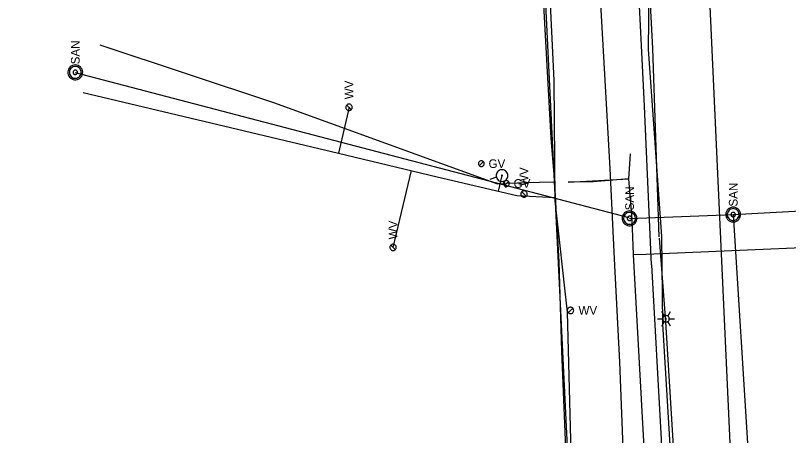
# Model space of a CAD drawing. Extents: x 596028 to 606371, y 330010 to 403088.
# Drawn here: x 604597.6 to 604941.1, y 334107.4 to 334294 of the extents above; entities that cross this region are included whole.
import ezdxf

# ---------------------------------------------------------------- set-up
doc = ezdxf.new("R2010")
doc.units = 0
for name, color, linetype in [('E_FTMS_Conduit', 7, 'Continuous'), ('E_LTG', 7, 'Continuous'), ('E_LTG_CID', 7, 'Continuous'), ('E_UTL_E_UG', 7, 'Continuous'), ('E_UTL_FO_UG_QWEST', 7, 'Continuous'), ('E_UTL_G', 7, 'Continuous'), ('E_UTL_G_UG', 7, 'Continuous'), ('E_UTL_SAN_MH', 7, 'Continuous'), ('E_UTL_SAN_UG', 7, 'Continuous'), ('E_UTL_SAN_UG_MMSD', 7, 'Continuous'), ('E_UTL_T_UG', 7, 'Continuous'), ('E_UTL_W', 7, 'Continuous'), ('E_UTL_W_UG', 7, 'Continuous'), ('E_UTL_WHydrant', 7, 'Continuous')]:
    doc.layers.add(name, color=color, linetype=linetype)

msp = doc.modelspace()

# ---------------------------------------------------------------- linework, layer by layer
at = {"layer": 'E_FTMS_Conduit'}
for points in [[(604884.79, 334195.8), (604878.86, 334279.06), (604879.25, 334317.86), (604874.33, 334402.45), (604871.01, 334441.38), (604869.22, 334499.65), (604867.19, 334547.69), (604865.66, 334623.82), (604860.3, 334662.92), (604859.68, 334742.73)], [(604896.64, 333466.11), (604897.17, 333555.99), (604901.76, 333584.15), (604905.09, 333639.3), (604905.9, 333684.1), (604904.77, 333712.67), (604904.93, 333775.72), (604905.22, 333800.4), (604903.67, 333828.24), (604898.91, 333896.44), (604894.79, 333935.39), (604893.25, 333968.09), (604888.86, 334043.3), (604889.85, 334080.96), (604885.17, 334157.03), (604884.79, 334195.8)]]:
    msp.add_lwpolyline(points, dxfattribs=at)
at = {"layer": 'E_LTG'}
for points in [[(604885.95, 334160.45), (604884.75, 334162.51)], [(604887.37, 334160.45), (604888.57, 334162.51)], [(604882.85, 334159.21), (604885.23, 334159.21)], [(604888.09, 334159.21), (604888.06, 334159.48), (604887.99, 334159.74), (604887.86, 334159.98), (604887.69, 334160.2), (604887.49, 334160.38), (604887.25, 334160.51), (604887, 334160.6), (604886.73, 334160.64), (604886.46, 334160.63), (604886.19, 334160.56), (604885.95, 334160.45), (604885.72, 334160.29), (604885.54, 334160.1), (604885.39, 334159.87), (604885.29, 334159.61), (604885.24, 334159.35), (604885.24, 334159.08), (604885.29, 334158.81), (604885.39, 334158.56), (604885.54, 334158.33), (604885.72, 334158.13), (604885.95, 334157.97), (604886.19, 334157.86), (604886.46, 334157.8), (604886.73, 334157.78), (604887, 334157.82), (604887.25, 334157.91), (604887.49, 334158.05), (604887.69, 334158.23), (604887.86, 334158.44), (604887.99, 334158.68), (604888.06, 334158.94), (604888.09, 334159.21)], [(604888.09, 334159.21), (604888.06, 334159.48), (604887.99, 334159.74), (604887.86, 334159.98), (604887.69, 334160.2), (604887.49, 334160.38), (604887.25, 334160.51), (604887, 334160.6), (604886.73, 334160.64), (604886.46, 334160.63), (604886.19, 334160.56), (604885.95, 334160.45), (604885.72, 334160.29), (604885.54, 334160.1), (604885.39, 334159.87), (604885.29, 334159.61), (604885.24, 334159.35), (604885.24, 334159.08), (604885.29, 334158.81), (604885.39, 334158.56), (604885.54, 334158.33), (604885.72, 334158.13), (604885.95, 334157.97), (604886.19, 334157.86), (604886.46, 334157.8), (604886.73, 334157.78), (604887, 334157.82), (604887.25, 334157.91), (604887.49, 334158.05), (604887.69, 334158.23), (604887.86, 334158.44), (604887.99, 334158.68), (604888.06, 334158.94), (604888.09, 334159.21)], [(604888.09, 334159.21), (604888.06, 334159.48), (604887.99, 334159.74), (604887.86, 334159.98), (604887.69, 334160.2), (604887.49, 334160.38), (604887.25, 334160.51), (604887, 334160.6), (604886.73, 334160.64), (604886.46, 334160.63), (604886.19, 334160.56), (604885.95, 334160.45), (604885.72, 334160.29), (604885.54, 334160.1), (604885.39, 334159.87), (604885.29, 334159.61), (604885.24, 334159.35), (604885.24, 334159.08), (604885.29, 334158.81), (604885.39, 334158.56), (604885.54, 334158.33), (604885.72, 334158.13), (604885.95, 334157.97), (604886.19, 334157.86), (604886.46, 334157.8), (604886.73, 334157.78), (604887, 334157.82), (604887.25, 334157.91), (604887.49, 334158.05), (604887.69, 334158.23), (604887.86, 334158.44), (604887.99, 334158.68), (604888.06, 334158.94), (604888.09, 334159.21)], [(604886.78, 334159.21), (604886.78, 334159.23), (604886.77, 334159.26), (604886.76, 334159.28), (604886.75, 334159.29), (604886.73, 334159.31), (604886.71, 334159.32), (604886.69, 334159.33), (604886.67, 334159.33), (604886.64, 334159.33), (604886.62, 334159.32), (604886.6, 334159.31), (604886.58, 334159.3), (604886.57, 334159.29), (604886.55, 334159.27), (604886.55, 334159.25), (604886.54, 334159.22), (604886.54, 334159.2), (604886.55, 334159.18), (604886.55, 334159.16), (604886.57, 334159.14), (604886.58, 334159.12), (604886.6, 334159.11), (604886.62, 334159.1), (604886.64, 334159.09), (604886.67, 334159.09), (604886.69, 334159.1), (604886.71, 334159.1), (604886.73, 334159.11), (604886.75, 334159.13), (604886.76, 334159.15), (604886.77, 334159.17), (604886.78, 334159.19), (604886.78, 334159.21)], [(604888.09, 334159.21), (604890.47, 334159.21)], [(604884.75, 334155.91), (604885.95, 334157.97)], [(604888.57, 334155.91), (604887.37, 334157.97)]]:
    msp.add_lwpolyline(points, dxfattribs=at)
at = {"layer": 'E_LTG_CID'}
for points in [[(604883.59, 334195.67), (604880.77, 334279.22), (604877.9, 334332.63), (604875.59, 334362.14), (604875.62, 334362.19), (604873, 334402.5), (604870.03, 334441.43), (604866.9, 334512.99), (604865.14, 334547.04), (604862.3, 334623.54), (604859.11, 334663.85), (604858.92, 334663.88), (604858.21, 334688.84), (604855.44, 334742.39)], [(604898.66, 333648.41), (604897.89, 333658.49), (604903.28, 333683.61), (604906.21, 333712.23), (604905.7, 333775.82), (604903.51, 333800.38), (604902.62, 333828.09), (604899.81, 333896.26), (604897.48, 333935.5), (604896.01, 333968.2), (604892.28, 334044.57), (604891.28, 334080.98), (604886.48, 334157.87), (604883.68, 334195.04)]]:
    msp.add_lwpolyline(points, dxfattribs=at)
at = {"layer": 'E_UTL_E_UG'}
msp.add_lwpolyline([(604877.02, 333463.99), (604875.73, 333577.42), (604874.92, 333635.7), (604875.14, 333666.02), (604873.55, 333754.91), (604872.54, 333805.97), (604872.79, 333814.74), (604870.78, 333892.12), (604869.22, 333968.06), (604869.63, 334026.67), (604868.32, 334082.91), (604866.08, 334139.89), (604863.78, 334185.83), (604861.75, 334225.99), (604854.45, 334356.74), (604852.93, 334403.87), (604848.36, 334473.21), (604845.77, 334520.34), (604845.77, 334520.23), (604841.27, 334614.96), (604838.91, 334672.58), (604835.72, 334731.86)], dxfattribs=at)
at = {"layer": 'E_UTL_FO_UG_QWEST'}
for points in [[(604880.24, 334183.25), (604876.98, 334256.9), (604873.2, 334330.88), (604873.06, 334361.71), (604869.66, 334408.48), (604865.91, 334483.81), (604863.36, 334557.53), (604860.02, 334633.27), (604855.03, 334705.91)], [(604064.36, 333597.95), (604125.52, 333607.24), (604222.69, 333622.89), (604294.58, 333635.82), (604348.76, 333642.01), (604429.81, 333649.86), (604519.71, 333664), (604602.19, 333686.85), (604652.71, 333705.68), (604723.21, 333725.29), (604801.25, 333748.09), (604835.09, 333762.42), (604848.03, 333769.94), (604883.85, 333785.99), (604890.17, 333789.47), (604890.94, 333790.11), (604892.16, 333796.08), (604892.06, 333804.65), (604893.55, 333818.96), (604893.11, 333877.27), (604889.73, 333952.96), (604886.58, 334030.08), (604884.67, 334105.68), (604880.28, 334183.13)]]:
    msp.add_lwpolyline(points, dxfattribs=at)
at = {"layer": 'E_UTL_G'}
for points in [[(604805.86, 334228.14), (604805.84, 334228.38), (604805.77, 334228.61), (604805.66, 334228.83), (604805.5, 334229.02), (604805.32, 334229.18), (604805.11, 334229.3), (604804.88, 334229.38), (604804.64, 334229.42), (604804.39, 334229.41), (604804.16, 334229.35), (604803.93, 334229.25), (604803.74, 334229.11), (604803.57, 334228.93), (604803.44, 334228.73), (604803.34, 334228.5), (604803.3, 334228.26), (604803.3, 334228.02), (604803.34, 334227.78), (604803.44, 334227.55), (604803.57, 334227.34), (604803.74, 334227.17), (604803.93, 334227.03), (604804.16, 334226.92), (604804.39, 334226.87), (604804.64, 334226.86), (604804.88, 334226.89), (604805.11, 334226.97), (604805.32, 334227.09), (604805.5, 334227.25), (604805.66, 334227.44), (604805.77, 334227.66), (604805.84, 334227.89), (604805.86, 334228.14)], [(604803.67, 334227.23), (604805.48, 334229.04)], [(604816.99, 334219.32), (604816.97, 334219.56), (604816.9, 334219.8), (604816.79, 334220.02), (604816.64, 334220.21), (604816.45, 334220.37), (604816.24, 334220.49), (604816.01, 334220.57), (604815.77, 334220.6), (604815.53, 334220.59), (604815.29, 334220.53), (604815.07, 334220.43), (604814.87, 334220.29), (604814.7, 334220.11), (604814.57, 334219.91), (604814.48, 334219.68), (604814.43, 334219.44), (604814.43, 334219.2), (604814.48, 334218.96), (604814.57, 334218.73), (604814.7, 334218.53), (604814.87, 334218.35), (604815.07, 334218.21), (604815.29, 334218.11), (604815.53, 334218.05), (604815.77, 334218.04), (604816.01, 334218.07), (604816.24, 334218.15), (604816.45, 334218.28), (604816.64, 334218.44), (604816.79, 334218.63), (604816.9, 334218.84), (604816.97, 334219.08), (604816.99, 334219.32)], [(604814.8, 334218.41), (604816.62, 334220.23)]]:
    msp.add_lwpolyline(points, dxfattribs=at)
at = {"layer": 'E_UTL_G_UG'}
for p, q in [((604846.79, 334022.5), (604815.57, 334656.09)), ((604843.17, 334219.95), (604870.15, 334221.36))]:
    msp.add_line(p, q, dxfattribs=at)
for points in [[(604635.16, 334280.95), (604712.2, 334255.32), (604811.79, 334219.2), (604815.71, 334219.32)], [(604870.15, 334221.36), (604870.79, 334232.44)], [(604853.45, 334022.92), (604864.06, 334023.58), (604880.04, 334023.53), (604877.77, 334085.98), (604874.7, 334142.31), (604872.13, 334187.75), (604871.53, 334203.36), (604870.15, 334221.36), (604854.2, 334220.08), (604843.17, 334219.95)], [(604853.45, 334022.92), (604864.06, 334023.58), (604880.04, 334023.53), (604877.77, 334085.98), (604874.7, 334142.31), (604872.13, 334187.75), (604871.53, 334203.36), (604870.15, 334221.36), (604854.2, 334220.08), (604843.17, 334219.95)], [(604837.06, 334219.87), (604830.47, 334219.8), (604815.71, 334219.32)], [(604877.78, 334187.91), (604995.48, 334193.01), (605021.24, 334194.51), (605035.38, 334195.48), (605042.27, 334195.61), (605062.39, 334196.8), (605076.03, 334197.48), (605095.32, 334198.25)], [(604877.78, 334187.91), (604995.48, 334193.01), (605021.24, 334194.51), (605035.38, 334195.48), (605042.27, 334195.61), (605062.39, 334196.8), (605076.03, 334197.48), (605095.32, 334198.25)], [(604872.13, 334187.77), (604877.78, 334187.91)]]:
    msp.add_lwpolyline(points, dxfattribs=at)
at = {"layer": 'E_UTL_SAN_MH'}
for points in [[(604624.17, 334272), (604623.55, 334271.94), (604622.95, 334271.76), (604622.39, 334271.47), (604621.9, 334271.09), (604621.49, 334270.61), (604621.17, 334270.07), (604620.97, 334269.48), (604620.88, 334268.86), (604620.91, 334268.23), (604621.05, 334267.62), (604621.32, 334267.05), (604621.68, 334266.54), (604622.13, 334266.1), (604622.66, 334265.77), (604623.24, 334265.53), (604623.86, 334265.41), (604624.49, 334265.41), (604625.1, 334265.53), (604625.69, 334265.77), (604626.21, 334266.1), (604626.67, 334266.54), (604627.03, 334267.05), (604627.29, 334267.62), (604627.44, 334268.23), (604627.47, 334268.86), (604627.38, 334269.48), (604627.18, 334270.07), (604626.86, 334270.61), (604626.45, 334271.09), (604625.96, 334271.47), (604625.4, 334271.76), (604624.8, 334271.94), (604624.17, 334272)], [(604624.17, 334271.34), (604623.67, 334271.29), (604623.19, 334271.15), (604622.75, 334270.92), (604622.35, 334270.61), (604622.02, 334270.23), (604621.77, 334269.8), (604621.61, 334269.32), (604621.54, 334268.82), (604621.56, 334268.32), (604621.68, 334267.84), (604621.89, 334267.38), (604622.18, 334266.97), (604622.54, 334266.62), (604622.96, 334266.35), (604623.43, 334266.17), (604623.92, 334266.07), (604624.42, 334266.07), (604624.92, 334266.17), (604625.38, 334266.35), (604625.81, 334266.62), (604626.17, 334266.97), (604626.46, 334267.38), (604626.67, 334267.84), (604626.79, 334268.32), (604626.81, 334268.82), (604626.74, 334269.32), (604626.57, 334269.8), (604626.32, 334270.23), (604626, 334270.61), (604625.6, 334270.92), (604625.15, 334271.15), (604624.67, 334271.29), (604624.17, 334271.34)], [(604624.17, 334269.69), (604623.99, 334269.67), (604623.81, 334269.62), (604623.64, 334269.53), (604623.49, 334269.42), (604623.37, 334269.27), (604623.27, 334269.11), (604623.21, 334268.93), (604623.18, 334268.75), (604623.19, 334268.56), (604623.24, 334268.38), (604623.32, 334268.2), (604623.43, 334268.05), (604623.56, 334267.92), (604623.72, 334267.82), (604623.89, 334267.75), (604624.08, 334267.71), (604624.27, 334267.71), (604624.45, 334267.75), (604624.63, 334267.82), (604624.79, 334267.92), (604624.92, 334268.05), (604625.03, 334268.2), (604625.11, 334268.38), (604625.15, 334268.56), (604625.16, 334268.75), (604625.14, 334268.93), (604625.07, 334269.11), (604624.98, 334269.27), (604624.86, 334269.42), (604624.71, 334269.53), (604624.54, 334269.62), (604624.36, 334269.67), (604624.17, 334269.69)], [(604870.42, 334207.14), (604869.8, 334207.08), (604869.2, 334206.9), (604868.64, 334206.62), (604868.15, 334206.23), (604867.74, 334205.75), (604867.42, 334205.21), (604867.22, 334204.62), (604867.13, 334204), (604867.16, 334203.37), (604867.31, 334202.76), (604867.57, 334202.19), (604867.93, 334201.68), (604868.38, 334201.25), (604868.91, 334200.91), (604869.49, 334200.67), (604870.11, 334200.55), (604870.74, 334200.55), (604871.35, 334200.67), (604871.94, 334200.91), (604872.46, 334201.25), (604872.92, 334201.68), (604873.28, 334202.19), (604873.54, 334202.76), (604873.69, 334203.37), (604873.72, 334204), (604873.63, 334204.62), (604873.43, 334205.21), (604873.11, 334205.75), (604872.7, 334206.23), (604872.21, 334206.62), (604871.65, 334206.9), (604871.05, 334207.08), (604870.42, 334207.14)], [(604916.47, 334208.81), (604915.84, 334208.76), (604915.24, 334208.58), (604914.68, 334208.29), (604914.19, 334207.9), (604913.78, 334207.43), (604913.47, 334206.89), (604913.26, 334206.29), (604913.17, 334205.67), (604913.2, 334205.05), (604913.35, 334204.44), (604913.61, 334203.86), (604913.97, 334203.35), (604914.43, 334202.92), (604914.96, 334202.58), (604915.54, 334202.35), (604916.15, 334202.23), (604916.78, 334202.23), (604917.4, 334202.35), (604917.98, 334202.58), (604918.51, 334202.92), (604918.96, 334203.35), (604919.33, 334203.86), (604919.59, 334204.44), (604919.73, 334205.05), (604919.76, 334205.67), (604919.68, 334206.29), (604919.47, 334206.89), (604919.16, 334207.43), (604918.75, 334207.9), (604918.25, 334208.29), (604917.69, 334208.58), (604917.09, 334208.76), (604916.47, 334208.81)], [(604916.47, 334208.15), (604915.97, 334208.11), (604915.49, 334207.97), (604915.04, 334207.74), (604914.65, 334207.43), (604914.32, 334207.05), (604914.07, 334206.61), (604913.9, 334206.14), (604913.83, 334205.64), (604913.86, 334205.14), (604913.97, 334204.65), (604914.18, 334204.19), (604914.47, 334203.79), (604914.84, 334203.44), (604915.26, 334203.17), (604915.72, 334202.98), (604916.22, 334202.89), (604916.72, 334202.89), (604917.21, 334202.98), (604917.68, 334203.17), (604918.1, 334203.44), (604918.46, 334203.79), (604918.75, 334204.19), (604918.96, 334204.65), (604919.08, 334205.14), (604919.11, 334205.64), (604919.03, 334206.14), (604918.87, 334206.61), (604918.62, 334207.05), (604918.29, 334207.43), (604917.9, 334207.74), (604917.45, 334207.97), (604916.97, 334208.11), (604916.47, 334208.15)], [(604870.42, 334206.48), (604869.92, 334206.43), (604869.44, 334206.29), (604869, 334206.06), (604868.6, 334205.75), (604868.27, 334205.37), (604868.02, 334204.94), (604867.86, 334204.46), (604867.79, 334203.97), (604867.81, 334203.46), (604867.93, 334202.98), (604868.14, 334202.52), (604868.43, 334202.11), (604868.79, 334201.76), (604869.21, 334201.49), (604869.68, 334201.31), (604870.17, 334201.21), (604870.68, 334201.21), (604871.17, 334201.31), (604871.63, 334201.49), (604872.06, 334201.76), (604872.42, 334202.11), (604872.71, 334202.52), (604872.92, 334202.98), (604873.04, 334203.46), (604873.06, 334203.97), (604872.99, 334204.46), (604872.83, 334204.94), (604872.57, 334205.37), (604872.25, 334205.75), (604871.85, 334206.06), (604871.41, 334206.29), (604870.92, 334206.43), (604870.42, 334206.48)], [(604870.42, 334204.83), (604870.24, 334204.81), (604870.06, 334204.76), (604869.89, 334204.67), (604869.74, 334204.56), (604869.62, 334204.41), (604869.52, 334204.25), (604869.46, 334204.07), (604869.44, 334203.89), (604869.44, 334203.7), (604869.49, 334203.52), (604869.57, 334203.34), (604869.68, 334203.19), (604869.81, 334203.06), (604869.97, 334202.96), (604870.15, 334202.89), (604870.33, 334202.85), (604870.52, 334202.85), (604870.7, 334202.89), (604870.88, 334202.96), (604871.04, 334203.06), (604871.17, 334203.19), (604871.28, 334203.34), (604871.36, 334203.52), (604871.4, 334203.7), (604871.41, 334203.89), (604871.39, 334204.07), (604871.32, 334204.25), (604871.23, 334204.41), (604871.11, 334204.56), (604870.96, 334204.67), (604870.79, 334204.76), (604870.61, 334204.81), (604870.42, 334204.83)], [(604916.47, 334206.5), (604916.28, 334206.49), (604916.1, 334206.43), (604915.93, 334206.35), (604915.79, 334206.23), (604915.66, 334206.09), (604915.57, 334205.93), (604915.51, 334205.75), (604915.48, 334205.56), (604915.49, 334205.37), (604915.53, 334205.19), (604915.61, 334205.02), (604915.72, 334204.87), (604915.86, 334204.74), (604916.01, 334204.63), (604916.19, 334204.56), (604916.37, 334204.53), (604916.56, 334204.53), (604916.75, 334204.56), (604916.92, 334204.63), (604917.08, 334204.74), (604917.22, 334204.87), (604917.33, 334205.02), (604917.4, 334205.19), (604917.45, 334205.37), (604917.46, 334205.56), (604917.43, 334205.75), (604917.37, 334205.93), (604917.27, 334206.09), (604917.15, 334206.23), (604917, 334206.35), (604916.84, 334206.43), (604916.66, 334206.49), (604916.47, 334206.5)]]:
    msp.add_lwpolyline(points, dxfattribs=at)
at = {"layer": 'E_UTL_SAN_UG'}
for p, q in [((604624.17, 334268.7), (604870.09, 334204.24)), ((604916.64, 334205.57), (605186.48, 334220.25)), ((604870.42, 334203.84), (604916.64, 334205.57)), ((604927.55, 334030.14), (604916.64, 334205.57))]:
    msp.add_line(p, q, dxfattribs=at)
at = {"layer": 'E_UTL_SAN_UG_MMSD'}
msp.add_lwpolyline([(604978.83, 333311.92), (604918.55, 334029.79), (604889.58, 334663.41)], dxfattribs=at)
at = {"layer": 'E_UTL_T_UG'}
msp.add_lwpolyline([(604844.73, 333915.07), (604844.08, 333962.32), (604842.41, 334031.55), (604842.27, 334098.22), (604840.37, 334144.9), (604839.13, 334184.46), (604837.03, 334221.52), (604835.65, 334239.39), (604831.76, 334309.5)], dxfattribs=at)
at = {"layer": 'E_UTL_W'}
for points in [[(604745.8, 334254.59), (604745.53, 334254.56), (604745.27, 334254.49), (604745.03, 334254.36), (604744.82, 334254.19), (604744.64, 334253.99), (604744.5, 334253.75), (604744.41, 334253.5), (604744.38, 334253.23), (604744.39, 334252.96), (604744.45, 334252.7), (604744.57, 334252.45), (604744.72, 334252.23), (604744.92, 334252.04), (604745.15, 334251.89), (604745.4, 334251.79), (604745.66, 334251.74), (604745.94, 334251.74), (604746.2, 334251.79), (604746.45, 334251.89), (604746.68, 334252.04), (604746.88, 334252.23), (604747.04, 334252.45), (604747.15, 334252.7), (604747.21, 334252.96), (604747.22, 334253.23), (604747.19, 334253.5), (604747.1, 334253.75), (604746.96, 334253.99), (604746.78, 334254.19), (604746.57, 334254.36), (604746.33, 334254.49), (604746.07, 334254.56), (604745.8, 334254.59)], [(604746.81, 334252.15), (604744.79, 334254.17)], [(604823.53, 334216.09), (604823.26, 334216.06), (604823, 334215.99), (604822.76, 334215.86), (604822.54, 334215.7), (604822.37, 334215.49), (604822.23, 334215.26), (604822.14, 334215), (604822.1, 334214.73), (604822.12, 334214.46), (604822.18, 334214.2), (604822.29, 334213.95), (604822.45, 334213.73), (604822.65, 334213.54), (604822.88, 334213.4), (604823.13, 334213.3), (604823.39, 334213.24), (604823.66, 334213.24), (604823.93, 334213.3), (604824.18, 334213.4), (604824.41, 334213.54), (604824.61, 334213.73), (604824.76, 334213.95), (604824.88, 334214.2), (604824.94, 334214.46), (604824.95, 334214.73), (604824.91, 334215), (604824.83, 334215.26), (604824.69, 334215.49), (604824.51, 334215.7), (604824.3, 334215.86), (604824.06, 334215.99), (604823.8, 334216.06), (604823.53, 334216.09)], [(604824.54, 334213.66), (604822.52, 334215.67)], [(604765.39, 334192.37), (604765.12, 334192.34), (604764.86, 334192.27), (604764.62, 334192.14), (604764.41, 334191.97), (604764.23, 334191.77), (604764.09, 334191.53), (604764, 334191.28), (604763.97, 334191.01), (604763.98, 334190.74), (604764.04, 334190.48), (604764.16, 334190.23), (604764.31, 334190.01), (604764.51, 334189.82), (604764.74, 334189.67), (604764.99, 334189.57), (604765.25, 334189.52), (604765.53, 334189.52), (604765.79, 334189.57), (604766.04, 334189.67), (604766.27, 334189.82), (604766.47, 334190.01), (604766.63, 334190.23), (604766.74, 334190.48), (604766.8, 334190.74), (604766.81, 334191.01), (604766.78, 334191.28), (604766.69, 334191.53), (604766.55, 334191.77), (604766.37, 334191.97), (604766.16, 334192.14), (604765.92, 334192.27), (604765.66, 334192.34), (604765.39, 334192.37)], [(604766.4, 334189.93), (604764.38, 334191.95)], [(604845.62, 334162.94), (604845.59, 334163.21), (604845.52, 334163.47), (604845.39, 334163.71), (604845.22, 334163.93), (604845.02, 334164.1), (604844.78, 334164.24), (604844.53, 334164.33), (604844.26, 334164.37), (604843.99, 334164.35), (604843.73, 334164.29), (604843.48, 334164.18), (604843.26, 334164.02), (604843.07, 334163.82), (604842.93, 334163.6), (604842.82, 334163.34), (604842.77, 334163.08), (604842.77, 334162.81), (604842.82, 334162.54), (604842.93, 334162.29), (604843.07, 334162.06), (604843.26, 334161.86), (604843.48, 334161.71), (604843.73, 334161.6), (604843.99, 334161.53), (604844.26, 334161.52), (604844.53, 334161.56), (604844.78, 334161.65), (604845.02, 334161.78), (604845.22, 334161.96), (604845.39, 334162.17), (604845.52, 334162.41), (604845.59, 334162.67), (604845.62, 334162.94)], [(604843.18, 334161.93), (604845.2, 334163.95)]]:
    msp.add_lwpolyline(points, dxfattribs=at)
at = {"layer": 'E_UTL_W_UG'}
for p, q in [((604627.73, 334259.78), (604741.14, 334232.84)), ((604812.15, 334215.94), (604813.77, 334222.84))]:
    msp.add_line(p, q, dxfattribs=at)
for points in [[(604846.62, 333845.73), (604845.91, 333962.63), (604845.14, 333993.13), (604845.77, 334042.88), (604845.13, 334077.17), (604842.87, 334162.23), (604837.44, 334211.69), (604837.01, 334265.02), (604832.72, 334352.02), (604829.86, 334407.8), (604827.89, 334453.7), (604825.43, 334498.81), (604822.75, 334554.4), (604821.56, 334581.06), (604817.29, 334667.8), (604815.06, 334708.63), (604813.04, 334742.82), (604812.12, 334767.3), (604810.04, 334815.66), (604808.35, 334858.79), (604806.58, 334923.66), (604806.18, 334938.53), (604802.65, 334960.89), (604797.31, 335097.75)], [(604745.8, 334253.16), (604741.14, 334232.84), (604784.95, 334222.29), (604820.41, 334214.01), (604837.36, 334213.13)], [(604765.39, 334190.94), (604773.6, 334225.03)]]:
    msp.add_lwpolyline(points, dxfattribs=at)
at = {"layer": 'E_UTL_WHydrant'}
for points in [[(604811.44, 334224.06), (604811.25, 334223.6), (604811.16, 334223.11), (604811.15, 334222.61), (604811.25, 334222.12), (604811.43, 334221.65), (604811.7, 334221.23), (604812.04, 334220.87), (604812.44, 334220.58), (604812.89, 334220.37), (604813.38, 334220.25), (604813.88, 334220.22), (604814.37, 334220.29), (604814.84, 334220.45), (604815.28, 334220.7), (604815.65, 334221.02), (604815.96, 334221.41), (604816.2, 334221.85), (604816.34, 334222.33), (604816.39, 334222.83), (604816.34, 334223.32), (604816.21, 334223.8), (604815.98, 334224.25), (604815.67, 334224.64), (604815.3, 334224.97), (604814.87, 334225.22), (604814.4, 334225.39), (604813.91, 334225.46), (604813.41, 334225.44), (604812.92, 334225.33), (604812.47, 334225.12), (604812.06, 334224.83), (604811.71, 334224.47), (604811.44, 334224.06)], [(604811.29, 334222.07), (604808.4, 334221.16)], [(604813.59, 334222.93), (604813.57, 334222.9), (604813.57, 334222.86), (604813.57, 334222.82), (604813.57, 334222.79), (604813.59, 334222.75), (604813.61, 334222.72), (604813.63, 334222.69), (604813.66, 334222.67), (604813.7, 334222.65), (604813.74, 334222.64), (604813.77, 334222.64), (604813.81, 334222.65), (604813.85, 334222.66), (604813.88, 334222.68), (604813.91, 334222.7), (604813.93, 334222.73), (604813.95, 334222.77), (604813.96, 334222.8), (604813.97, 334222.84), (604813.96, 334222.88), (604813.95, 334222.92), (604813.94, 334222.95), (604813.91, 334222.98), (604813.88, 334223), (604813.85, 334223.02), (604813.81, 334223.04), (604813.78, 334223.04), (604813.74, 334223.04), (604813.7, 334223.03), (604813.67, 334223.02), (604813.64, 334222.99), (604813.61, 334222.97), (604813.59, 334222.93)], [(604814.54, 334220.37), (604815.45, 334217.48)]]:
    msp.add_lwpolyline(points, dxfattribs=at)

# ---------------------------------------------------------------- texts
at = {"layer": 'E_UTL_G'}
for p in [(604807.78, 334226.21), (604818.92, 334217.4)]:
    msp.add_text('GV', height=3.85, dxfattribs=at).set_placement(p)
at = {"layer": 'E_UTL_SAN_MH'}
for p in [(604626.12, 334272.26), (604872.37, 334207.4), (604918.41, 334209.08)]:
    msp.add_text('SAN', height=3.849, rotation=90, dxfattribs=at).set_placement(p)
at = {"layer": 'E_UTL_W'}
for p in [(604747.73, 334256.73), (604825.45, 334218.23), (604767.32, 334194.51)]:
    msp.add_text('WV', height=3.85, rotation=90, dxfattribs=at).set_placement(p)
msp.add_text('WV', height=3.85, dxfattribs=at).set_placement((604847.76, 334161.02))

doc.saveas('drawing.dxf')
